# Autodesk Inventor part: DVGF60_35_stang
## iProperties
Created: 2010-04
Part Number: DVGF60_35_stang
Document SubType Name: Modeling
Designer: TB
Mass: 317.932 g
Surface Area: 379.639 cm^2
Volume: 317.932 cm^3
Density: 1 g/cm^3
Author: TB
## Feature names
1. Revolution1
2. Fillet1
3. Revolution2
4. Extrusion1
5. Extrusion2
6. Extrusion3
7. Chamfer2
8. Chamfer3
9. Chamfer4
